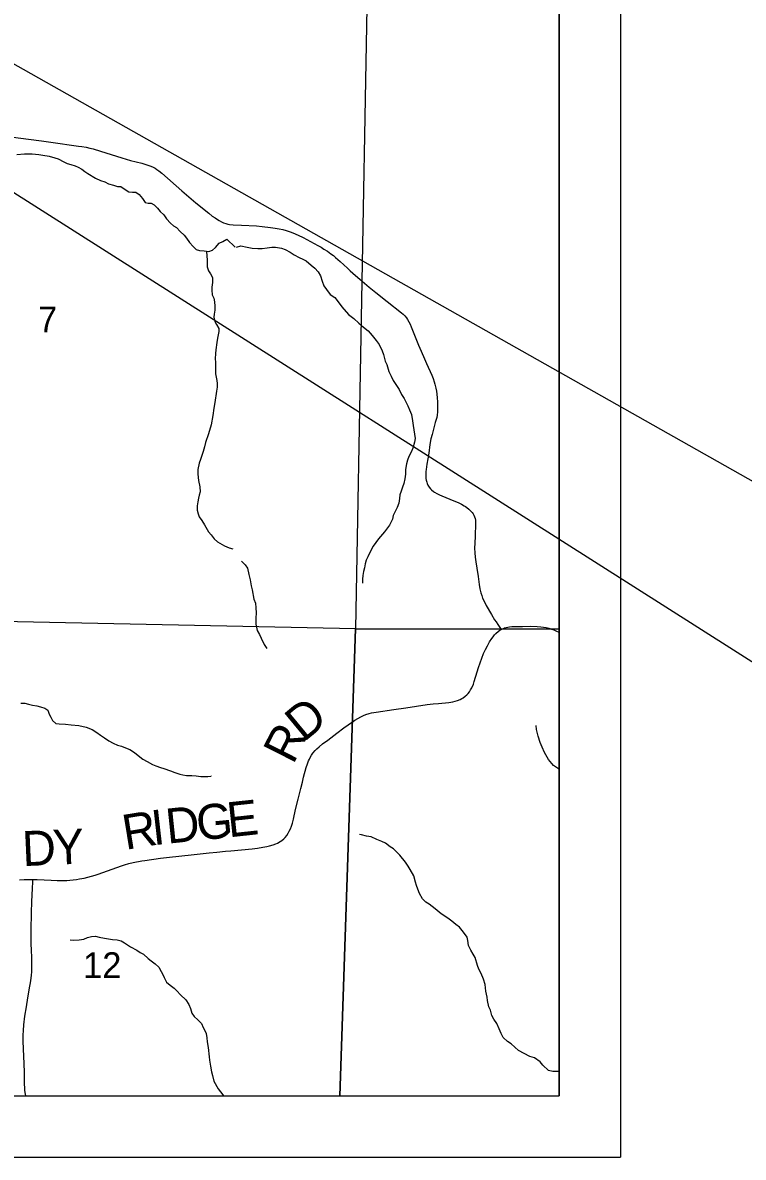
# Model space of a CAD drawing. Extents: x 0 to 34, y 0 to 22.
# Drawn here: x 8.027 to 9.2, y 14 to 15.844 of the extents above; entities that cross this region are included whole.
import ezdxf

# ---------------------------------------------------------------- set-up
doc = ezdxf.new("R2010")
doc.units = 0
for name, color, linetype in [('GM_X_Corporation', 7, 'Continuous'), ('GM_X_County_Road_Text', 7, 'Continuous'), ('GM_X_Interchange_Ramps', 7, 'Continuous'), ('GM_X_Interstate_Route', 7, 'Continuous'), ('GM_X_Major_Lake', 7, 'Continuous'), ('GM_X_Minor_Lake', 7, 'Continuous'), ('GM_X_Township_Road_Text', 7, 'Continuous'), ('GM_X_Unincorporated_Text', 7, 'Continuous'), ('SH_Cut_Line', 7, 'Continuous'), ('SH_Data', 7, 'Continuous')]:
    doc.layers.add(name, color=color, linetype=linetype)

msp = doc.modelspace()

# ---------------------------------------------------------------- linework, layer by layer
at = {"layer": 'GM_X_Corporation'}
for points in [[(8.0118, 15.658), (8.0367, 15.6547), (8.058, 15.652), (8.0734, 15.6498), (8.1183, 15.6435), (8.1238, 15.6428), (8.1309, 15.6416), (8.1367, 15.6403), (8.1421, 15.6392), (8.1542, 15.6353), (8.1884, 15.6244), (8.2029, 15.62), (8.2211, 15.6156), (8.2294, 15.6133), (8.2327, 15.6121), (8.2358, 15.6109), (8.2394, 15.6094), (8.2427, 15.6077), (8.2457, 15.6055), (8.2489, 15.6032), (8.2537, 15.5995), (8.2864, 15.5706), (8.3091, 15.5513), (8.33, 15.5344), (8.3357, 15.5299), (8.3402, 15.5267), (8.3441, 15.5242), (8.3471, 15.5224), (8.351, 15.5203), (8.3542, 15.5189), (8.3577, 15.5176), (8.361, 15.5167), (8.364, 15.5161), (8.3699, 15.5156), (8.3833, 15.5149), (8.4079, 15.5137), (8.4167, 15.5129), (8.4304, 15.5112), (8.4381, 15.5102), (8.4447, 15.509), (8.4506, 15.5078), (8.4559, 15.5062), (8.4623, 15.5041), (8.4669, 15.5025), (8.4754, 15.4989), (8.4835, 15.495), (8.5072, 15.4822), (8.5128, 15.479), (8.5172, 15.4762), (8.5231, 15.4725), (8.5288, 15.4685), (8.5327, 15.4656), (8.5364, 15.4625), (8.5438, 15.4557), (8.5556, 15.4449), (8.5599, 15.4409), (8.5688, 15.4332), (8.5758, 15.4271), (8.5833, 15.4208), (8.5912, 15.4142), (8.6017, 15.4054), (8.62, 15.3908), (8.6434, 15.3727), (8.6465, 15.3701), (8.6492, 15.3674), (8.6517, 15.3644), (8.6535, 15.3618), (8.6557, 15.3581), (8.6576, 15.3542), (8.6595, 15.3498), (8.6712, 15.3202), (8.6733, 15.315), (8.6795, 15.3013), (8.6844, 15.2904), (8.693, 15.2711), (8.695, 15.2658), (8.6967, 15.2604), (8.6979, 15.2565), (8.6995, 15.2502), (8.7006, 15.2451), (8.7012, 15.2406), (8.7017, 15.2345), (8.7019, 15.2278), (8.7019, 15.2258)], [(8.7019, 15.2258), (8.7021, 15.2219), (8.7022, 15.2164), (8.7021, 15.2116), (8.7014, 15.2064), (8.7008, 15.2026), (8.6985, 15.1943), (8.6932, 15.1749), (8.6914, 15.1677), (8.6898, 15.1584), (8.6879, 15.1446), (8.6863, 15.1351), (8.6849, 15.1266), (8.6836, 15.1179), (8.6833, 15.1145), (8.6831, 15.1104), (8.6831, 15.1068), (8.6834, 15.1033), (8.6838, 15.1003), (8.6846, 15.0973), (8.6854, 15.0952), (8.6866, 15.0926), (8.6887, 15.0893), (8.6908, 15.0866), (8.6924, 15.085), (8.6954, 15.0824), (8.6974, 15.081), (8.7011, 15.0788), (8.7054, 15.0766), (8.7093, 15.0749), (8.7222, 15.0696), (8.7287, 15.0671), (8.7355, 15.0643), (8.7413, 15.0613), (8.7454, 15.059), (8.7478, 15.0576), (8.7501, 15.056), (8.7532, 15.0535), (8.7559, 15.0509), (8.7586, 15.0478), (8.7601, 15.0456), (8.7614, 15.0435), (8.7625, 15.0412), (8.7633, 15.0383), (8.7639, 15.0353), (8.7641, 15.0321), (8.7641, 15.0285), (8.7639, 15.0238), (8.7636, 15.0162), (8.7632, 15.0096), (8.7626, 14.9982), (8.7625, 14.9899), (8.763, 14.9822), (8.7636, 14.9756), (8.7645, 14.9677), (8.766, 14.9577), (8.7682, 14.9438), (8.77, 14.931), (8.7711, 14.9237), (8.7724, 14.9175), (8.774, 14.9129), (8.7754, 14.9089), (8.7773, 14.9047), (8.7815, 14.8971), (8.7902, 14.882), (8.795, 14.8737), (8.7975, 14.8701), (8.8004, 14.8658), (8.8058, 14.858)], [(8.0221, 14.451), (8.0299, 14.4513), (8.0442, 14.4514), (8.0507, 14.4513), (8.0736, 14.4503), (8.0835, 14.45), (8.0927, 14.4499), (8.0992, 14.4501), (8.1039, 14.4504), (8.1095, 14.4508), (8.1148, 14.4515), (8.1199, 14.4524), (8.1273, 14.4536), (8.1335, 14.4551), (8.1452, 14.4584), (8.1499, 14.46), (8.188, 14.4735), (8.1932, 14.4752), (8.2002, 14.4773), (8.2071, 14.4789), (8.221, 14.4817), (8.226, 14.4825), (8.2518, 14.4861), (8.2663, 14.4879), (8.3013, 14.4918), (8.3307, 14.4948), (8.3431, 14.496), (8.3572, 14.4974), (8.3658, 14.4982), (8.4009, 14.5016), (8.4095, 14.5025), (8.4181, 14.5038), (8.4243, 14.505), (8.4288, 14.5061), (8.4348, 14.5078), (8.4389, 14.5093), (8.4421, 14.5107), (8.4461, 14.5131), (8.4489, 14.5149), (8.4521, 14.5174), (8.4544, 14.5199), (8.457, 14.5229), (8.4593, 14.5267), (8.461, 14.53), (8.4628, 14.5336), (8.4646, 14.5382), (8.466, 14.5429), (8.4678, 14.5495), (8.4714, 14.5651), (8.4757, 14.582), (8.48, 14.5993), (8.4825, 14.6098), (8.4843, 14.6179), (8.4884, 14.6333), (8.4904, 14.6395), (8.4923, 14.6443), (8.4937, 14.6473), (8.4949, 14.6498), (8.4973, 14.6538), (8.4996, 14.657), (8.503, 14.6609), (8.5058, 14.6637), (8.5097, 14.6673), (8.5151, 14.6718), (8.5235, 14.6782), (8.5383, 14.6894), (8.5498, 14.698), (8.5566, 14.7028), (8.5678, 14.7104), (8.5726, 14.7133), (8.5773, 14.7158), (8.5818, 14.718), (8.5858, 14.7196), (8.5909, 14.7212), (8.595, 14.7224), (8.6021, 14.7235), (8.6311, 14.7278), (8.6504, 14.7307), (8.6851, 14.7357), (8.6952, 14.7368), (8.7038, 14.7378), (8.7208, 14.7394), (8.7268, 14.7402), (8.7308, 14.7412), (8.7349, 14.7424), (8.7389, 14.7442), (8.7415, 14.7455), (8.7437, 14.7469), (8.747, 14.7493), (8.7496, 14.7517), (8.7518, 14.754), (8.7539, 14.7567), (8.7559, 14.7599), (8.7577, 14.7628), (8.7606, 14.7689), (8.762, 14.7731), (8.7666, 14.7889), (8.769, 14.796), (8.7713, 14.8034), (8.7743, 14.8115), (8.7772, 14.8188), (8.7803, 14.8253), (8.7834, 14.8315), (8.7869, 14.8379), (8.7905, 14.8431), (8.7925, 14.8459), (8.795, 14.849), (8.7972, 14.8513), (8.8014, 14.8551), (8.8035, 14.8566), (8.8058, 14.858)], [(8.8058, 14.858), (8.8093, 14.8596), (8.8113, 14.8604), (8.8138, 14.8612), (8.8165, 14.8618), (8.8191, 14.8622), (8.8233, 14.8626), (8.833, 14.8627), (8.8405, 14.8629), (8.8528, 14.8631), (8.8645, 14.8627), (8.8702, 14.8623), (8.8746, 14.8617), (8.8789, 14.861), (8.8833, 14.8599), (8.8875, 14.8586), (8.8912, 14.8573), (8.8947, 14.8557), (8.8993, 14.8533), (8.9, 14.8529)]]:
    msp.add_lwpolyline(points, dxfattribs=at)
at = {"layer": 'GM_X_Interchange_Ramps'}
msp.add_lwpolyline([(6.5113, 14.1), (8.9, 14.1), (8.9, 17.8921), (8.5492, 17.9006), (8.3297, 17.9059), (7.6027, 17.9156), (6.5943, 17.9356), (6.5883, 17.471), (6.5647, 16.5359), (6.5572, 16.1864), (6.5411, 15.4243), (6.5389, 15.3228)], close=True, dxfattribs=at)
at = {"layer": 'GM_X_Interstate_Route'}
msp.add_lwpolyline([(8.0324, 14.1), (8.0317, 14.1027), (8.0309, 14.1086), (8.0305, 14.1231), (8.0301, 14.1384), (8.0295, 14.1648), (8.0289, 14.1751), (8.0281, 14.1899), (8.028, 14.1985), (8.0285, 14.206), (8.0293, 14.2153), (8.0311, 14.2294), (8.0335, 14.2446), (8.0357, 14.259), (8.0373, 14.2684), (8.0385, 14.2752), (8.0401, 14.2838), (8.0411, 14.2911), (8.0417, 14.296), (8.0421, 14.3016), (8.0425, 14.31), (8.0421, 14.326), (8.0419, 14.3358), (8.0414, 14.348), (8.0411, 14.3667), (8.0412, 14.3735), (8.0417, 14.3929), (8.0419, 14.4016), (8.0422, 14.4112), (8.0425, 14.4185), (8.0427, 14.4232), (8.043, 14.4296), (8.0432, 14.4338), (8.0435, 14.4396), (8.0438, 14.4448), (8.0441, 14.4494), (8.0442, 14.4514)], dxfattribs=at)
at = {"layer": 'GM_X_Minor_Lake'}
msp.add_lwpolyline([(7.5725, 15.8874), (8.5869, 15.8686), (8.5685, 14.859), (7.5466, 14.8803)], close=True, dxfattribs=at)
at = {"layer": 'GM_X_Township_Road_Text'}
for points in [[(8.018, 15.63), (8.0301, 15.6309), (8.0426, 15.6311), (8.0536, 15.6301), (8.0604, 15.6287), (8.0706, 15.627), (8.0794, 15.6244), (8.0851, 15.623), (8.0943, 15.6178), (8.0996, 15.6152), (8.1057, 15.6138), (8.1129, 15.6116), (8.1178, 15.6094), (8.1236, 15.6061), (8.1286, 15.602), (8.1335, 15.599), (8.1457, 15.5916), (8.1538, 15.5875), (8.161, 15.5857), (8.1671, 15.582), (8.1751, 15.5799), (8.1815, 15.5781), (8.1872, 15.5778), (8.1922, 15.574), (8.2002, 15.5692), (8.2059, 15.5685), (8.2116, 15.5686), (8.2166, 15.5649), (8.222, 15.5581), (8.2266, 15.5521), (8.2315, 15.5507), (8.2365, 15.5507), (8.2414, 15.5478), (8.2464, 15.5429), (8.251, 15.5373), (8.2568, 15.5316), (8.2614, 15.5252), (8.2676, 15.5181), (8.2726, 15.514), (8.2775, 15.5114), (8.2833, 15.5046), (8.2902, 15.4986), (8.2941, 15.4938), (8.2987, 15.4866), (8.3045, 15.4806), (8.3095, 15.4757), (8.3152, 15.4739), (8.3224, 15.4733), (8.3304, 15.4722), (8.336, 15.4746), (8.3412, 15.4789), (8.3468, 15.4858), (8.3528, 15.4886), (8.3596, 15.4925), (8.373, 15.4793)], [(8.3263, 15.473), (8.3271, 15.4646), (8.3275, 15.4585), (8.3277, 15.4471), (8.3297, 15.4406), (8.3328, 15.4357), (8.3363, 15.4301), (8.3364, 15.4217), (8.335, 15.4145), (8.3351, 15.4095), (8.3356, 15.4019), (8.3383, 15.3962), (8.3395, 15.3905), (8.34, 15.3833), (8.3397, 15.3769), (8.3387, 15.3704), (8.3384, 15.3654), (8.34, 15.3586), (8.3427, 15.3537), (8.3462, 15.3473), (8.3463, 15.3423), (8.3445, 15.3313), (8.3431, 15.3244), (8.3418, 15.3122), (8.3411, 15.3065), (8.3405, 15.2977), (8.3409, 15.2924), (8.3412, 15.2734), (8.3433, 15.2627), (8.3437, 15.2578), (8.3438, 15.2517), (8.3428, 15.2452), (8.34, 15.2269), (8.3382, 15.2174), (8.3365, 15.2059), (8.3337, 15.1906), (8.3294, 15.1761), (8.325, 15.162), (8.3233, 15.1547), (8.3207, 15.1474), (8.3189, 15.1406), (8.3164, 15.134), (8.3142, 15.1283), (8.3124, 15.118), (8.3122, 15.1104), (8.3135, 15.0998), (8.3155, 15.0895), (8.316, 15.0815), (8.3142, 15.0762), (8.3131, 15.0712), (8.3121, 15.0655), (8.3114, 15.059), (8.3111, 15.0518), (8.3127, 15.0461), (8.3143, 15.0412), (8.3189, 15.0348), (8.3232, 15.028), (8.3298, 15.0167), (8.3337, 15.0118), (8.3391, 15.0054), (8.3444, 15.0005), (8.3559, 14.9938), (8.3635, 14.9905), (8.3692, 14.9887)], [(8.375, 15.4793), (8.3824, 15.4816), (8.3923, 15.4793), (8.4006, 15.4777), (8.4097, 15.4769), (8.4169, 15.4769), (8.4253, 15.478), (8.4325, 15.4791), (8.4386, 15.4791), (8.4481, 15.4776), (8.4545, 15.4753), (8.4624, 15.4711), (8.4689, 15.4669), (8.4772, 15.4623), (8.4829, 15.46), (8.4886, 15.4573), (8.4965, 15.45), (8.5026, 15.4451), (8.5082, 15.4394), (8.5116, 15.4329), (8.5146, 15.4238), (8.5172, 15.4165), (8.5214, 15.4104), (8.5274, 15.4024), (8.535, 15.3975), (8.5403, 15.3902), (8.5463, 15.3822), (8.5576, 15.37), (8.566, 15.3631), (8.5743, 15.3559), (8.5818, 15.3494), (8.5894, 15.3433), (8.5958, 15.3357), (8.6022, 15.3273), (8.6071, 15.3208), (8.612, 15.3105), (8.6143, 15.3048), (8.6169, 15.2942), (8.6199, 15.2885), (8.6229, 15.2774), (8.6266, 15.2694), (8.63, 15.2626), (8.6342, 15.2561), (8.6398, 15.2481), (8.6436, 15.2397), (8.6481, 15.2333), (8.6541, 15.2211), (8.6564, 15.2146), (8.6598, 15.2074), (8.6612, 15.1971), (8.6627, 15.1895), (8.6649, 15.1751), (8.6657, 15.1682), (8.6649, 15.1625), (8.6618, 15.1527), (8.6591, 15.1462), (8.6557, 15.139), (8.6534, 15.1329), (8.6515, 15.1269), (8.6503, 15.1177), (8.6502, 15.1105), (8.6491, 15.1025), (8.6475, 15.0953), (8.6452, 15.0893), (8.6429, 15.0828), (8.641, 15.0767), (8.6402, 15.0707), (8.639, 15.0634), (8.6367, 15.0562), (8.634, 15.0505), (8.6302, 15.043), (8.6287, 15.0373), (8.6241, 15.0274), (8.6161, 15.0168), (8.6062, 15.0054), (8.5974, 14.9933), (8.5924, 14.9842), (8.5886, 14.9762), (8.5859, 14.9705), (8.5847, 14.9645), (8.5832, 14.958), (8.582, 14.9523), (8.5805, 14.9455), (8.5801, 14.9394), (8.58, 14.9329)], [(8.3833, 14.969), (8.3893, 14.9632), (8.3931, 14.9575), (8.3953, 14.9473), (8.3972, 14.9385), (8.399, 14.9286), (8.4009, 14.9222), (8.4035, 14.907), (8.4061, 14.9005), (8.4068, 14.8933), (8.4072, 14.8849), (8.4064, 14.8762), (8.4067, 14.8667), (8.409, 14.8564), (8.4127, 14.8495), (8.4154, 14.8438), (8.4203, 14.8336), (8.4244, 14.8271)], [(8.0245, 14.7383), (8.031, 14.738), (8.0371, 14.7366), (8.0435, 14.7348), (8.0504, 14.7338), (8.0564, 14.732), (8.0633, 14.7302), (8.0683, 14.7268), (8.0706, 14.7204), (8.0733, 14.7151), (8.0757, 14.7098), (8.0811, 14.7053), (8.0868, 14.7043), (8.097, 14.7037), (8.1065, 14.703), (8.1186, 14.7017), (8.1304, 14.6992), (8.1403, 14.6952), (8.1479, 14.6904), (8.154, 14.6859), (8.1602, 14.6818)], [(8.9, 14.6306), (8.899, 14.6312), (8.891, 14.6366), (8.8827, 14.6468), (8.876, 14.6579), (8.8722, 14.6666), (8.8692, 14.6743), (8.8658, 14.6842), (8.8632, 14.6952), (8.8625, 14.7016)], [(8.1602, 14.6818), (8.1674, 14.6769), (8.1743, 14.6732), (8.1815, 14.6696), (8.188, 14.6681), (8.1945, 14.6656), (8.2017, 14.6626), (8.209, 14.6578), (8.2151, 14.6529), (8.2228, 14.6473), (8.2296, 14.6433), (8.2388, 14.6385), (8.2437, 14.6363), (8.2517, 14.6337), (8.2567, 14.6319), (8.2677, 14.6282), (8.2749, 14.6253), (8.2829, 14.6228), (8.2879, 14.6217), (8.2939, 14.6207), (8.3023, 14.6204), (8.3095, 14.6198), (8.3171, 14.6187), (8.3288, 14.6189), (8.3337, 14.6197), (8.3332, 14.6201)], [(8.9, 14.1393), (8.8973, 14.1395), (8.8897, 14.1395), (8.8829, 14.1411), (8.8734, 14.1495), (8.8689, 14.1552), (8.8598, 14.1617), (8.8522, 14.164), (8.8431, 14.1686), (8.834, 14.1735), (8.8219, 14.1842), (8.8159, 14.188), (8.8087, 14.1949), (8.8057, 14.201), (8.8023, 14.2086), (8.7986, 14.2174), (8.7937, 14.2246), (8.7903, 14.2307), (8.7884, 14.2391), (8.7858, 14.2448), (8.7832, 14.2547), (8.7828, 14.2604), (8.781, 14.2699), (8.7795, 14.2809), (8.7769, 14.2896), (8.7731, 14.2988), (8.7693, 14.306), (8.7671, 14.3117), (8.7634, 14.3247), (8.76, 14.3304), (8.7566, 14.3365), (8.7528, 14.3444), (8.7517, 14.3521), (8.7506, 14.3578), (8.7446, 14.3661), (8.7381, 14.3738), (8.7317, 14.3783), (8.7257, 14.3837), (8.7189, 14.3886), (8.7079, 14.3955), (8.6984, 14.4039), (8.6886, 14.4116), (8.6829, 14.4146), (8.6776, 14.4203), (8.6731, 14.4287), (8.6701, 14.4359), (8.6679, 14.4417), (8.6664, 14.4474), (8.6634, 14.4572), (8.6577, 14.4675), (8.6543, 14.4732), (8.6502, 14.4797), (8.6411, 14.4908), (8.6306, 14.5014), (8.6249, 14.5045), (8.6177, 14.5106), (8.6113, 14.5133), (8.6033, 14.5167), (8.5942, 14.5206), (8.5866, 14.5217), (8.5783, 14.524), (8.575, 14.5245)], [(8.1044, 14.3532), (8.1104, 14.3529), (8.1195, 14.3535), (8.1267, 14.3547), (8.1327, 14.3571), (8.1391, 14.3591), (8.1459, 14.3596), (8.152, 14.3578), (8.1604, 14.3564), (8.1733, 14.3539), (8.1812, 14.3533), (8.1873, 14.3518), (8.193, 14.3485), (8.203, 14.3418), (8.2133, 14.3366), (8.2186, 14.3329), (8.224, 14.3299), (8.2313, 14.3232), (8.2366, 14.3191), (8.2428, 14.3143), (8.2489, 14.309), (8.2528, 14.3018), (8.2555, 14.2969), (8.2575, 14.292), (8.2614, 14.2845), (8.2675, 14.28), (8.2736, 14.2751), (8.2779, 14.2703), (8.284, 14.2639), (8.2925, 14.256), (8.2979, 14.2485), (8.3002, 14.2417), (8.3026, 14.2341), (8.3061, 14.2288), (8.3122, 14.2232), (8.318, 14.2172), (8.3211, 14.2112), (8.3235, 14.2059), (8.3258, 14.201), (8.3267, 14.1941), (8.3275, 14.1877), (8.3292, 14.1786), (8.3309, 14.1634), (8.3314, 14.158), (8.333, 14.1482), (8.3347, 14.1391), (8.3359, 14.133), (8.3383, 14.1239), (8.3453, 14.1114), (8.353, 14.1013), (8.3541, 14.1)]]:
    msp.add_lwpolyline(points, dxfattribs=at)
at = {"layer": 'GM_X_Unincorporated_Text'}
for points in [[(8.9, 14.8583), (8.9, 15.8651), (8.5869, 15.8686), (8.5685, 14.859)], [(7.5285, 14.1), (8.5434, 14.1), (8.5685, 14.859), (7.5466, 14.8803)], [(8.5434, 14.1), (8.9, 14.1), (8.9, 14.8583), (8.5685, 14.859)]]:
    msp.add_lwpolyline(points, close=True, dxfattribs=at)
at = {"layer": 'SH_Cut_Line'}
msp.add_lwpolyline([(2.1, 17.9098), (2.1, 14.1), (8.9, 14.1), (8.9, 17.8921), (8.5492, 17.9006), (8.3297, 17.9059), (7.6027, 17.9156), (6.5943, 17.9356), (6.24, 17.9427), (6.0729, 17.9463), (5.6339, 17.9555), (5.3871, 17.9608), (4.994, 17.969), (4.9368, 17.9702), (4.9267, 17.9702), (4.5919, 17.9719), (4.4481, 17.9728), (4.1825, 17.9744), (3.7128, 17.9822), (3.7063, 17.8588), (3.604, 17.8577), (2.9484, 17.8857), (2.6711, 17.8975), (2.4376, 17.9025)], close=True, dxfattribs=at)
at = {"layer": 'SH_Data'}
for p, q in [((9, 21), (9, 14)), ((8.9, 20.9), (8.9, 14.1)), ((2.1, 14.1), (8.9, 14.1)), ((2, 14), (9, 14))]:
    msp.add_line(p, q, dxfattribs=at)
msp.add_lwpolyline([(9.2998, 15.0505), (5.0551, 17.4465), (9.2998, 14.751)], close=True, dxfattribs=at)

# ---------------------------------------------------------------- texts
at = {"layer": 'GM_X_County_Road_Text'}
for s, height, p in [('7', 0.0419, (8.0524, 15.3408)), ('12', 0.04186, (8.1257, 14.2914))]:
    msp.add_text(s, height=height, rotation=0, dxfattribs=at).set_placement(p)
at = {"layer": 'GM_X_Major_Lake'}
for s, rotation, p in [('D', 39.6008, (8.4845, 14.6739)), ('R', 63.1435, (8.4672, 14.6371)), ('D', 5.9226, (8.263, 14.5096)), ('G', 5.8933, (8.3127, 14.5147)), ('E', 6.1537, (8.3627, 14.5199)), ('R', 9.3186, (8.1946, 14.4995)), ('I', 6.485, (8.2399, 14.507)), ('Y', 2.3758, (8.0776, 14.4754)), ('D', 2.5763, (8.0277, 14.4731))]:
    msp.add_text(s, height=0.0568, rotation=rotation, dxfattribs=at).set_placement(p)

doc.saveas('drawing.dxf')
